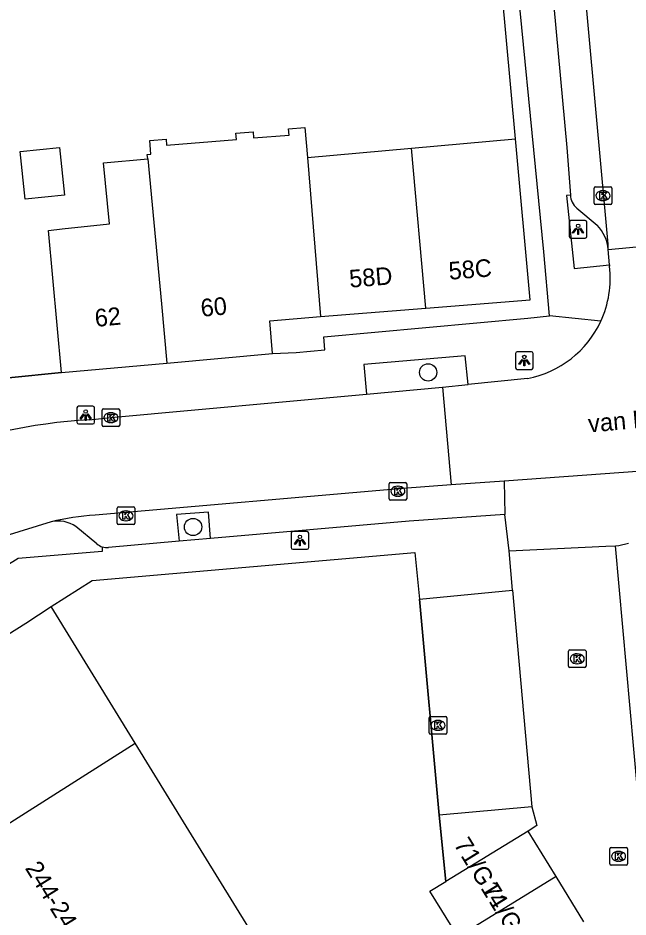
# Model space of a CAD drawing. Extents: x 160379 to 161131, y 383940 to 384849.
# Drawn here: x 160571.2 to 160605.8, y 384465.3 to 384516.2 of the extents above; entities that cross this region are included whole.
import ezdxf

# ---------------------------------------------------------------- set-up
doc = ezdxf.new("R2010")
doc.units = 0
for name, color, linetype in [('IMGEO_Boom', 7, 'Continuous'), ('IMGEO_Erf', 7, 'Continuous'), ('IMGEO_Hek', 7, 'Continuous'), ('IMGEO_Kolk', 7, 'Continuous'), ('IMGEO_Lichtpunt', 7, 'Continuous'), ('IMGEO_Muur', 7, 'Continuous'), ('IMGEO_Openbare_ruimte_label', 7, 'Continuous'), ('IMGEO_Pand', 7, 'Continuous'), ('IMGEO_Pand_nummerreeks', 7, 'Continuous'), ('IMGEO_Parkeervlak_open', 7, 'Continuous'), ('IMGEO_Rijbaan_lokaal_open', 7, 'Continuous'), ('IMGEO_Voetpad_open', 7, 'Continuous')]:
    doc.layers.add(name, color=color, linetype=linetype)

msp = doc.modelspace()

# ---------------------------------------------------------------- linework, layer by layer
at = {"layer": 'IMGEO_Boom'}
for centre in [(160594.425, 384496.111), (160581.106, 384487.353)]:
    msp.add_circle(centre, 0.489, dxfattribs=at)
at = {"layer": 'IMGEO_Erf'}
msp.add_lwpolyline([(160599.373, 384509.341), (160598.334, 384520.705), (160598.213, 384522.234)], dxfattribs=at)
at = {"layer": 'IMGEO_Hek'}
msp.add_lwpolyline([(160573.642, 384496.096), (160570.648, 384495.799)], dxfattribs=at)
at = {"layer": 'IMGEO_Kolk'}
for p, q in [((160603.833, 384505.697), (160603.833, 384506.549)), ((160603.908, 384506.623), (160604.76, 384506.623)), ((160604.834, 384506.549), (160604.834, 384505.697)), ((160604.321, 384506.403), (160604.346, 384506.403)), ((160604.76, 384505.623), (160603.908, 384505.623)), ((160604.344, 384505.843), (160604.319, 384505.843)), ((160575.949, 384493.121), (160575.949, 384493.973)), ((160576.024, 384494.047), (160576.876, 384494.047)), ((160576.437, 384493.827), (160576.462, 384493.827)), ((160576.95, 384493.973), (160576.95, 384493.121)), ((160576.46, 384493.267), (160576.435, 384493.267)), ((160576.876, 384493.047), (160576.024, 384493.047)), ((160592.209, 384488.952), (160592.209, 384489.804)), ((160592.284, 384489.878), (160593.136, 384489.878)), ((160593.21, 384489.804), (160593.21, 384488.952)), ((160592.697, 384489.658), (160592.722, 384489.658)), ((160593.136, 384488.878), (160592.284, 384488.878)), ((160592.72, 384489.098), (160592.695, 384489.098)), ((160576.802, 384487.561), (160576.802, 384488.413)), ((160576.877, 384488.487), (160577.729, 384488.487)), ((160577.29, 384488.267), (160577.315, 384488.267)), ((160577.803, 384488.413), (160577.803, 384487.561)), ((160577.313, 384487.707), (160577.288, 384487.707)), ((160577.729, 384487.487), (160576.877, 384487.487)), ((160602.372, 384479.462), (160602.372, 384480.314)), ((160602.447, 384480.388), (160603.299, 384480.388)), ((160602.86, 384480.168), (160602.885, 384480.168)), ((160603.373, 384480.314), (160603.373, 384479.462)), ((160602.883, 384479.608), (160602.858, 384479.608)), ((160603.299, 384479.388), (160602.447, 384479.388)), ((160594.483, 384475.689), (160594.483, 384476.541)), ((160594.558, 384476.615), (160595.41, 384476.615)), ((160595.484, 384476.541), (160595.484, 384475.689)), ((160594.971, 384476.395), (160594.996, 384476.395)), ((160595.41, 384475.615), (160594.558, 384475.615)), ((160594.994, 384475.835), (160594.969, 384475.835)), ((160604.716, 384468.27), (160604.716, 384469.122)), ((160604.791, 384469.196), (160605.643, 384469.196)), ((160605.204, 384468.976), (160605.229, 384468.976)), ((160605.717, 384469.122), (160605.717, 384468.27)), ((160605.227, 384468.416), (160605.202, 384468.416)), ((160605.643, 384468.196), (160604.791, 384468.196))]:
    msp.add_line(p, q, dxfattribs=at)
for points in [[(160603.833, 384505.697), (160603.833, 384506.549)], [(160603.908, 384506.623), (160604.76, 384506.623)], [(160604.834, 384506.549), (160604.834, 384505.697)], [(160604.154, 384506.323), (160604.277, 384506.323), (160604.277, 384506.172), (160604.407, 384506.323), (160604.571, 384506.323), (160604.425, 384506.172), (160604.578, 384505.923), (160604.426, 384505.923), (160604.341, 384506.087), (160604.277, 384506.02), (160604.277, 384505.923), (160604.154, 384505.923), (160604.154, 384506.323)], [(160604.76, 384505.623), (160603.908, 384505.623)], [(160575.949, 384493.121), (160575.949, 384493.973)], [(160576.024, 384494.047), (160576.876, 384494.047)], [(160576.27, 384493.747), (160576.393, 384493.747), (160576.393, 384493.596), (160576.523, 384493.747), (160576.687, 384493.747), (160576.541, 384493.596), (160576.694, 384493.347), (160576.542, 384493.347), (160576.457, 384493.511), (160576.393, 384493.444), (160576.393, 384493.347), (160576.27, 384493.347), (160576.27, 384493.747)], [(160576.95, 384493.973), (160576.95, 384493.121)], [(160576.876, 384493.047), (160576.024, 384493.047)], [(160592.209, 384488.952), (160592.209, 384489.804)], [(160592.284, 384489.878), (160593.136, 384489.878)], [(160593.21, 384489.804), (160593.21, 384488.952)], [(160592.53, 384489.578), (160592.653, 384489.578), (160592.653, 384489.427), (160592.783, 384489.578), (160592.947, 384489.578), (160592.801, 384489.427), (160592.954, 384489.178), (160592.802, 384489.178), (160592.717, 384489.342), (160592.653, 384489.275), (160592.653, 384489.178), (160592.53, 384489.178), (160592.53, 384489.578)], [(160593.136, 384488.878), (160592.284, 384488.878)], [(160576.802, 384487.561), (160576.802, 384488.413)], [(160576.877, 384488.487), (160577.729, 384488.487)], [(160577.123, 384488.187), (160577.246, 384488.187), (160577.246, 384488.036), (160577.376, 384488.187), (160577.54, 384488.187), (160577.394, 384488.036), (160577.547, 384487.787), (160577.395, 384487.787), (160577.31, 384487.951), (160577.246, 384487.884), (160577.246, 384487.787), (160577.123, 384487.787), (160577.123, 384488.187)], [(160577.803, 384488.413), (160577.803, 384487.561)], [(160577.729, 384487.487), (160576.877, 384487.487)], [(160602.372, 384479.462), (160602.372, 384480.314)], [(160602.447, 384480.388), (160603.299, 384480.388)], [(160602.693, 384480.088), (160602.816, 384480.088), (160602.816, 384479.937), (160602.946, 384480.088), (160603.11, 384480.088), (160602.964, 384479.937), (160603.117, 384479.688), (160602.965, 384479.688), (160602.88, 384479.852), (160602.816, 384479.785), (160602.816, 384479.688), (160602.693, 384479.688), (160602.693, 384480.088)], [(160603.373, 384480.314), (160603.373, 384479.462)], [(160603.299, 384479.388), (160602.447, 384479.388)], [(160594.483, 384475.689), (160594.483, 384476.541)], [(160594.558, 384476.615), (160595.41, 384476.615)], [(160595.484, 384476.541), (160595.484, 384475.689)], [(160594.804, 384476.315), (160594.927, 384476.315), (160594.927, 384476.164), (160595.057, 384476.315), (160595.221, 384476.315), (160595.075, 384476.164), (160595.228, 384475.915), (160595.076, 384475.915), (160594.991, 384476.079), (160594.927, 384476.012), (160594.927, 384475.915), (160594.804, 384475.915), (160594.804, 384476.315)], [(160595.41, 384475.615), (160594.558, 384475.615)], [(160604.716, 384468.27), (160604.716, 384469.122)], [(160604.791, 384469.196), (160605.643, 384469.196)], [(160605.037, 384468.896), (160605.16, 384468.896), (160605.16, 384468.745), (160605.29, 384468.896), (160605.454, 384468.896), (160605.308, 384468.745), (160605.461, 384468.496), (160605.309, 384468.496), (160605.224, 384468.66), (160605.16, 384468.593), (160605.16, 384468.496), (160605.037, 384468.496), (160605.037, 384468.896)], [(160605.717, 384469.122), (160605.717, 384468.27)], [(160605.643, 384468.196), (160604.791, 384468.196)]]:
    msp.add_lwpolyline(points, dxfattribs=at)
for centre, start, end in [((160603.91, 384506.547), 91.552, 178.448), ((160603.91, 384506.547), 91.552, 178.448), ((160604.758, 384506.547), 1.552, 88.448), ((160604.758, 384506.547), 1.552, 88.448), ((160603.91, 384505.699), 181.552, 268.448), ((160603.91, 384505.699), 181.552, 268.448), ((160604.758, 384505.699), 271.552, 358.448), ((160604.758, 384505.699), 271.552, 358.448), ((160576.026, 384493.971), 91.552, 178.448), ((160576.026, 384493.971), 91.552, 178.448), ((160576.874, 384493.971), 1.552, 88.448), ((160576.874, 384493.971), 1.552, 88.448), ((160576.026, 384493.123), 181.552, 268.448), ((160576.026, 384493.123), 181.552, 268.448), ((160576.874, 384493.123), 271.552, 358.448), ((160576.874, 384493.123), 271.552, 358.448), ((160592.286, 384489.802), 91.552, 178.448), ((160592.286, 384489.802), 91.552, 178.448), ((160593.134, 384489.802), 1.552, 88.448), ((160593.134, 384489.802), 1.552, 88.448), ((160592.286, 384488.954), 181.552, 268.448), ((160592.286, 384488.954), 181.552, 268.448), ((160593.134, 384488.954), 271.552, 358.448), ((160593.134, 384488.954), 271.552, 358.448), ((160576.879, 384488.411), 91.552, 178.448), ((160576.879, 384488.411), 91.552, 178.448), ((160577.727, 384488.411), 1.552, 88.448), ((160577.727, 384488.411), 1.552, 88.448), ((160576.879, 384487.563), 181.552, 268.448), ((160576.879, 384487.563), 181.552, 268.448), ((160577.727, 384487.563), 271.552, 358.448), ((160577.727, 384487.563), 271.552, 358.448), ((160602.449, 384480.312), 91.552, 178.448), ((160602.449, 384480.312), 91.552, 178.448), ((160603.297, 384480.312), 1.552, 88.448), ((160603.297, 384480.312), 1.552, 88.448), ((160602.449, 384479.464), 181.552, 268.448), ((160602.449, 384479.464), 181.552, 268.448), ((160603.297, 384479.464), 271.552, 358.448), ((160603.297, 384479.464), 271.552, 358.448), ((160594.56, 384476.539), 91.552, 178.448), ((160594.56, 384476.539), 91.552, 178.448), ((160595.408, 384476.539), 1.552, 88.448), ((160595.408, 384476.539), 1.552, 88.448), ((160594.56, 384475.691), 181.552, 268.448), ((160594.56, 384475.691), 181.552, 268.448), ((160595.408, 384475.691), 271.552, 358.448), ((160595.408, 384475.691), 271.552, 358.448), ((160604.793, 384469.12), 91.552, 178.448), ((160604.793, 384469.12), 91.552, 178.448), ((160605.641, 384469.12), 1.552, 88.448), ((160605.641, 384469.12), 1.552, 88.448), ((160604.793, 384468.272), 181.552, 268.448), ((160604.793, 384468.272), 181.552, 268.448), ((160605.641, 384468.272), 271.552, 358.448), ((160605.641, 384468.272), 271.552, 358.448)]:
    msp.add_arc(centre, 0.0765, start, end, dxfattribs=at)
for centre, major_axis, ratio, start_param, end_param in [((160604.32, 384506.123), (-0.387, 0.002), 0.722429, 4.712389, 7.853982), ((160604.345, 384506.123), (-0.39, 0.002), 0.717154, 1.570796, 4.712389), ((160576.436, 384493.547), (-0.387, 0.002), 0.722429, 4.712389, 7.853982), ((160576.461, 384493.547), (-0.39, 0.002), 0.717154, 1.570796, 4.712389), ((160592.696, 384489.378), (-0.387, 0.002), 0.722429, 4.712389, 7.853982), ((160592.721, 384489.378), (-0.39, 0.002), 0.717154, 1.570796, 4.712389), ((160577.289, 384487.987), (-0.387, 0.002), 0.722429, 4.712389, 7.853982), ((160577.314, 384487.987), (-0.39, 0.002), 0.717154, 1.570796, 4.712389), ((160602.859, 384479.888), (-0.387, 0.002), 0.722429, 4.712389, 7.853982), ((160602.884, 384479.888), (-0.39, 0.002), 0.717154, 1.570796, 4.712389), ((160594.97, 384476.115), (-0.387, 0.002), 0.722429, 4.712389, 7.853982), ((160594.995, 384476.115), (-0.39, 0.002), 0.717154, 1.570796, 4.712389), ((160605.203, 384468.696), (-0.387, 0.002), 0.722429, 4.712389, 7.853982), ((160605.228, 384468.696), (-0.39, 0.002), 0.717154, 1.570796, 4.712389)]:
    msp.add_ellipse(centre, major_axis=major_axis, ratio=ratio, start_param=start_param, end_param=end_param, dxfattribs=at)
at = {"layer": 'IMGEO_Lichtpunt'}
for p, q in [((160602.426, 384504.619), (160602.426, 384503.812)), ((160602.426, 384504.619), (160602.426, 384503.812)), ((160603.328, 384504.714), (160602.52, 384504.714)), ((160603.328, 384504.714), (160602.52, 384504.714)), ((160603.422, 384503.812), (160603.422, 384504.619)), ((160603.422, 384503.812), (160603.422, 384504.619)), ((160602.52, 384503.718), (160603.328, 384503.718)), ((160602.52, 384503.718), (160603.328, 384503.718)), ((160599.378, 384497.185), (160599.378, 384496.378)), ((160599.378, 384497.185), (160599.378, 384496.378)), ((160600.28, 384497.28), (160599.472, 384497.28)), ((160600.28, 384497.28), (160599.472, 384497.28)), ((160600.374, 384496.378), (160600.374, 384497.185)), ((160600.374, 384496.378), (160600.374, 384497.185)), ((160599.472, 384496.284), (160600.28, 384496.284)), ((160599.472, 384496.284), (160600.28, 384496.284)), ((160574.525, 384494.096), (160574.525, 384493.289)), ((160574.525, 384494.096), (160574.525, 384493.289)), ((160575.427, 384494.191), (160574.619, 384494.191)), ((160575.427, 384494.191), (160574.619, 384494.191)), ((160575.521, 384493.289), (160575.521, 384494.096)), ((160575.521, 384493.289), (160575.521, 384494.096)), ((160574.619, 384493.195), (160575.427, 384493.195)), ((160574.619, 384493.195), (160575.427, 384493.195)), ((160586.661, 384486.995), (160586.661, 384486.188)), ((160586.661, 384486.995), (160586.661, 384486.188)), ((160587.563, 384487.09), (160586.755, 384487.09)), ((160587.563, 384487.09), (160586.755, 384487.09)), ((160587.657, 384486.188), (160587.657, 384486.995)), ((160587.657, 384486.188), (160587.657, 384486.995)), ((160586.755, 384486.094), (160587.563, 384486.094)), ((160586.755, 384486.094), (160587.563, 384486.094))]:
    msp.add_line(p, q, dxfattribs=at)
for points in [[(160602.8, 384504.283), (160602.839, 384504.255), (160602.651, 384503.993), (160602.613, 384504.02), (160602.8, 384504.283)], [(160602.902, 384504.235), (160602.949, 384504.235), (160602.949, 384503.913), (160602.902, 384503.913), (160602.902, 384504.235)], [(160603.012, 384504.255), (160603.05, 384504.282), (160603.237, 384504.02), (160603.198, 384503.992), (160603.012, 384504.255)], [(160599.752, 384496.849), (160599.791, 384496.821), (160599.603, 384496.559), (160599.565, 384496.586), (160599.752, 384496.849)], [(160599.854, 384496.801), (160599.901, 384496.801), (160599.901, 384496.479), (160599.854, 384496.479), (160599.854, 384496.801)], [(160599.964, 384496.821), (160600.002, 384496.848), (160600.189, 384496.586), (160600.15, 384496.558), (160599.964, 384496.821)], [(160574.899, 384493.76), (160574.938, 384493.732), (160574.75, 384493.47), (160574.712, 384493.497), (160574.899, 384493.76)], [(160575.111, 384493.732), (160575.149, 384493.759), (160575.336, 384493.497), (160575.297, 384493.469), (160575.111, 384493.732)], [(160575.001, 384493.712), (160575.048, 384493.712), (160575.048, 384493.39), (160575.001, 384493.39), (160575.001, 384493.712)], [(160587.035, 384486.659), (160587.074, 384486.631), (160586.886, 384486.369), (160586.848, 384486.396), (160587.035, 384486.659)], [(160587.137, 384486.611), (160587.184, 384486.611), (160587.184, 384486.289), (160587.137, 384486.289), (160587.137, 384486.611)], [(160587.247, 384486.631), (160587.285, 384486.658), (160587.472, 384486.396), (160587.433, 384486.368), (160587.247, 384486.631)]]:
    msp.add_lwpolyline(points, dxfattribs=at)
for centre in [(160602.925, 384504.417), (160599.877, 384496.983), (160575.024, 384493.894), (160587.16, 384486.793)]:
    msp.add_circle(centre, 0.0994, dxfattribs=at)
for centre, start, end in [((160602.52, 384504.619), 90, 180), ((160602.52, 384504.619), 90, 180), ((160603.328, 384504.619), 0, 90), ((160603.328, 384504.619), 0, 90), ((160602.52, 384503.812), 180, 270), ((160602.52, 384503.812), 180, 270), ((160603.328, 384503.812), 270, 0), ((160603.328, 384503.812), 270, 360), ((160599.472, 384497.185), 90, 180), ((160599.472, 384497.185), 90, 180), ((160600.28, 384497.185), 0, 90), ((160600.28, 384497.185), 0, 90), ((160599.472, 384496.378), 180, 270), ((160599.472, 384496.378), 180, 270), ((160600.28, 384496.378), 270, 0), ((160600.28, 384496.378), 270, 360), ((160574.619, 384494.096), 90, 180), ((160574.619, 384494.096), 90, 180), ((160575.427, 384494.096), 0, 90), ((160575.427, 384494.096), 0, 90), ((160574.619, 384493.289), 180, 270), ((160574.619, 384493.289), 180, 270), ((160575.427, 384493.289), 270, 0), ((160575.427, 384493.289), 270, 360), ((160586.755, 384486.995), 90, 180), ((160586.755, 384486.995), 90, 180), ((160587.563, 384486.995), 0, 90), ((160587.563, 384486.995), 0, 90), ((160586.755, 384486.188), 180, 270), ((160586.755, 384486.188), 180, 270), ((160587.563, 384486.188), 270, 0), ((160587.563, 384486.188), 270, 360)]:
    msp.add_arc(centre, 0.0946, start, end, dxfattribs=at)
at = {"layer": 'IMGEO_Muur'}
for points in [[(160573.057, 384482.848), (160575.396, 384484.318), (160593.68, 384485.917), (160593.943, 384483.267)], [(160593.943, 384483.267), (160595.048, 384471.027)], [(160595.048, 384471.027), (160595.423, 384467.279)]]:
    msp.add_lwpolyline(points, dxfattribs=at)
at = {"layer": 'IMGEO_Pand'}
for points in [[(160578.535, 384508.214), (160578.512, 384508.456), (160578.716, 384508.473), (160578.651, 384509.251), (160579.578, 384509.328), (160579.607, 384508.979), (160583.563, 384509.309), (160583.533, 384509.657), (160584.505, 384509.738), (160584.534, 384509.39), (160586.543, 384509.557), (160586.514, 384509.906), (160587.441, 384509.983), (160587.583, 384508.278)], [(160593.478, 384508.81), (160599.373, 384509.341)], [(160594.295, 384499.748), (160600.213, 384500.218), (160599.373, 384509.341)], [(160573.529, 384508.855), (160573.812, 384506.149), (160571.584, 384505.916), (160571.301, 384508.621), (160573.529, 384508.855)], [(160587.583, 384508.278), (160593.478, 384508.81)], [(160594.295, 384499.748), (160593.478, 384508.81)], [(160573.642, 384496.096), (160572.915, 384504.155), (160573.688, 384504.236), (160576.364, 384504.518), (160576.034, 384507.975), (160578.535, 384508.214)], [(160578.535, 384508.214), (160579.32, 384500), (160579.619, 384496.642)], [(160587.583, 384508.278), (160588.333, 384499.274)], [(160588.333, 384499.274), (160594.295, 384499.748)], [(160585.602, 384497.19), (160585.448, 384499.034), (160588.333, 384499.274)], [(160579.619, 384496.642), (160585.602, 384497.19)], [(160573.642, 384496.096), (160579.619, 384496.642)], [(160563.179, 384476.631), (160566.551, 384478.706), (160565.76, 384479.98), (160568.759, 384481.842), (160569.579, 384480.63), (160571.622, 384481.907), (160573.057, 384482.848)], [(160577.816, 384475.113), (160573.057, 384482.848)], [(160567.965, 384468.864), (160577.816, 384475.113)], [(160585.272, 384463.014), (160580.715, 384470.401), (160577.816, 384475.113)], [(160600.098, 384470.118), (160595.423, 384467.279)], [(160601.676, 384467.554), (160600.098, 384470.118)], [(160596.119, 384464.134), (160594.521, 384466.731), (160595.423, 384467.279)], [(160601.676, 384467.554), (160596.119, 384464.134)], [(160603.254, 384464.99), (160601.676, 384467.554)]]:
    msp.add_lwpolyline(points, dxfattribs=at)
at = {"layer": 'IMGEO_Parkeervlak_open'}
for points in [[(160602.847, 384505.414), (160604.002, 384504.451)], [(160582.094, 384486.697), (160581.976, 384488.202), (160580.173, 384488.06), (160580.315, 384486.542)], [(160575.654, 384486.395), (160574.469, 384487.382)], [(160595.048, 384471.027), (160593.943, 384483.267)]]:
    msp.add_lwpolyline(points, dxfattribs=at)
for centre, radius, start, end in [((160603.495, 384506.181), 1.005, 181.4486, 229.8133), ((160602.352, 384502.869), 2.286, 5.1305, 43.8013), ((160573.458, 384485.863), 1.825, 56.3687, 102.3821), ((160576.215, 384487.049), 0.861, 229.3813, 252.7961)]:
    msp.add_arc(centre, radius, start, end, dxfattribs=at)
at = {"layer": 'IMGEO_Rijbaan_lokaal_open'}
for points in [[(160604.629, 384503.073), (160604.636, 384503.37), (160603.161, 384519.524), (160601.069, 384542.207), (160600.825, 384545.276)], [(160604.629, 384503.073), (160609.643, 384503.536)], [(160604.696, 384502.209), (160604.629, 384503.073)], [(160604.696, 384502.209), (160604.703, 384502.121)], [(160595.234, 384495.267), (160596.698, 384495.419)], [(160600.055, 384495.76), (160596.698, 384495.419)], [(160575.218, 384493.428), (160576.45, 384493.547), (160590.942, 384494.886)], [(160590.942, 384494.886), (160595.234, 384495.267)], [(160595.234, 384495.267), (160595.74, 384489.734)], [(160608.33, 384490.653), (160605.489, 384490.447), (160598.726, 384489.957)], [(160595.74, 384489.734), (160592.999, 384489.53), (160575.552, 384488.021)], [(160598.726, 384489.957), (160595.74, 384489.734)], [(160573.067, 384487.645), (160570.445, 384486.828)], [(160599.016, 384485.995), (160604.495, 384486.268), (160605.034, 384486.295)], [(160625.012, 384435.703), (160622.73, 384441.551), (160618.364, 384452.741), (160611.288, 384464.731), (160606.501, 384472.146), (160606.297, 384472.463), (160605.034, 384486.295)], [(160599.198, 384483.777), (160599.016, 384485.995)], [(160599.198, 384483.777), (160600.301, 384471.506)], [(160600.301, 384471.506), (160600.591, 384470.438), (160600.098, 384470.118)]]:
    msp.add_lwpolyline(points, dxfattribs=at)
for centre, radius, start, end in [((160598.95, 384501.437), 5.794, 335.1946, 6.7827), ((160598.96, 384501.442), 5.786, 280.9048, 335.1045), ((160577.224, 384460.774), 32.716, 93.5149, 110.7424), ((160576.398, 384474.031), 14.015, 93.4599, 103.7481)]:
    msp.add_arc(centre, radius, start, end, dxfattribs=at)
at = {"layer": 'IMGEO_Voetpad_open'}
for points in [[(160601.299, 384499.323), (160600.989, 384502.935), (160599.078, 384522.405), (160597.158, 384544.586), (160596.904, 384547.52), (160547.519, 384605.522), (160544.872, 384608.601), (160534.548, 384620.664)], [(160599.222, 384542.055), (160602.278, 384508.847), (160602.491, 384506.156)], [(160602.491, 384506.156), (160602.275, 384506.124), (160602.709, 384502), (160604.696, 384502.209)], [(160585.602, 384497.19), (160586.953, 384497.229), (160588.577, 384497.391), (160588.524, 384498.128), (160600.078, 384499.191), (160601.299, 384499.323)], [(160604.209, 384499.006), (160601.299, 384499.323)], [(160596.698, 384495.419), (160596.524, 384497.057), (160590.791, 384496.562), (160590.942, 384494.886)], [(160561.401, 384493.811), (160563.454, 384495.131), (160570.648, 384495.799), (160573.642, 384496.096)], [(160598.726, 384489.957), (160598.78, 384488.066)], [(160598.78, 384488.066), (160593.355, 384487.679), (160582.094, 384486.697)], [(160599.016, 384485.995), (160598.78, 384488.066)], [(160582.094, 384486.697), (160580.315, 384486.542)], [(160575.96, 384486.226), (160575.962, 384485.957), (160571.191, 384485.564), (160568.922, 384484.167), (160568.673, 384484.303)], [(160580.315, 384486.542), (160576.323, 384486.194)], [(160605.034, 384486.295), (160605.234, 384486.305), (160605.786, 384486.439)], [(160573.057, 384482.848), (160575.396, 384484.318), (160593.68, 384485.917), (160593.943, 384483.267)], [(160593.943, 384483.267), (160599.198, 384483.777)], [(160600.301, 384471.506), (160595.048, 384471.027)], [(160595.423, 384467.279), (160595.048, 384471.027)]]:
    msp.add_lwpolyline(points, dxfattribs=at)
msp.add_arc((160576.217, 384487.068), 0.88, 253.0194, 276.9049, dxfattribs=at)

# ---------------------------------------------------------------- texts
at = {"layer": 'IMGEO_Openbare_ruimte_label'}
msp.add_text('van Kinsbergenstraat', height=1, rotation=5.1062, dxfattribs=at).set_placement((160603.534, 384492.703))
at = {"layer": 'IMGEO_Pand_nummerreeks'}
for s, rotation, p in [('58C', 4.5436, (160595.625, 384501.358)), ('58D', 4.5436, (160589.99, 384500.91)), ('60', 5.4603, (160581.583, 384499.257)), ('62', 5.4546, (160575.582, 384498.684)), ('71/G14', 301.6045, (160595.853, 384469.374)), ('244-244D', 301.6844, (160571.557, 384468.03)), ('71/G13', 301.6056, (160597.441, 384466.794))]:
    msp.add_text(s, height=1, rotation=rotation, dxfattribs=at).set_placement(p)

doc.saveas('drawing.dxf')
